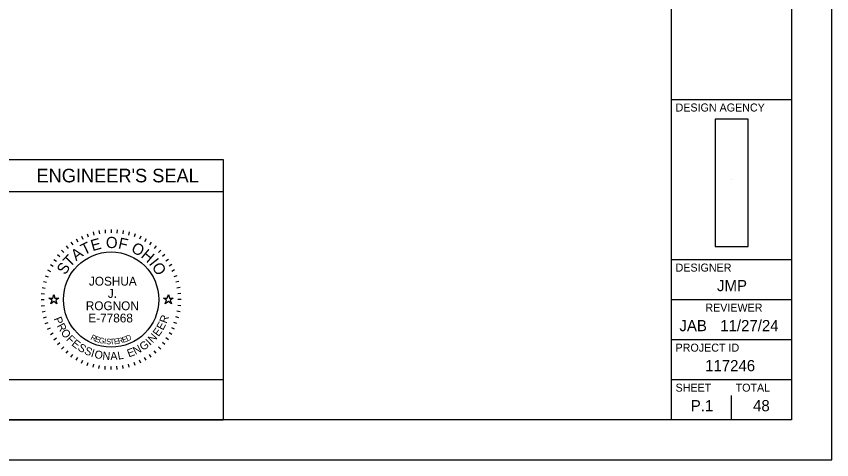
# Model space of a CAD drawing. Extents: x 0 to 34, y 0 to 22.
# Drawn here: x 23.82 to 34, y 0 to 5.54 of the extents above; entities that cross this region are included whole.
import ezdxf

# ---------------------------------------------------------------- set-up
doc = ezdxf.new("R2010")
doc.units = 0
for name, color, linetype in [('Default', 7, 'Continuous'), ('SH_Border', 7, 'Continuous'), ('SH_Cut_Line', 7, 'Continuous'), ('SH_Data', 7, 'Continuous'), ('SH_Text', 7, 'Continuous')]:
    doc.layers.add(name, color=color, linetype=linetype)

msp = doc.modelspace()

# ---------------------------------------------------------------- linework, layer by layer
at = {"layer": 'Default'}
for points in [[(24.224, 2.02), (24.271, 2.02), (24.285, 2.065), (24.299, 2.02), (24.346, 2.02), (24.308, 1.992), (24.323, 1.948), (24.285, 1.975), (24.247, 1.948), (24.262, 1.992)], [(25.654, 2.02), (25.701, 2.02), (25.715, 2.065), (25.729, 2.02), (25.776, 2.02), (25.738, 1.992), (25.753, 1.948), (25.715, 1.975), (25.677, 1.948), (25.692, 1.992)]]:
    msp.add_lwpolyline(points, close=True, dxfattribs=at)
at = {"layer": 'SH_Border'}
for p, q in [((32, 0.5), (32, 21.5)), ((32, 4.5), (33.5, 4.5)), ((32, 2.5), (33.5, 2.5)), ((32, 2), (33.5, 2)), ((32, 1.5), (33.5, 1.5)), ((32, 1), (33.5, 1))]:
    msp.add_line(p, q, dxfattribs=at)
msp.add_lwpolyline([(1.5, 21.5), (33.5, 21.5), (33.5, 0.5), (1.5, 0.5)], close=True, dxfattribs=at)
at = {"layer": 'SH_Cut_Line'}
msp.add_lwpolyline([(0, 0), (34, 0), (34, 22), (0, 22)], close=True, dxfattribs=at)
at = {"layer": 'SH_Data'}
for p, q in [((23.6, 3.75), (26.4, 3.75)), ((26.4, 3.75), (26.4, 0.5)), ((32.75, 3.5), (32.75, 3.5)), ((23.6, 3.35), (26.4, 3.35)), ((24.848, 2.862), (24.855, 2.822)), ((24.924, 2.872), (24.927, 2.832)), ((25, 2.875), (25, 2.835)), ((25.076, 2.872), (25.073, 2.832)), ((25.152, 2.862), (25.145, 2.822)), ((24.563, 2.758), (24.583, 2.723)), ((24.63, 2.793), (24.647, 2.757)), ((24.701, 2.822), (24.714, 2.785)), ((24.774, 2.845), (24.784, 2.807)), ((25.226, 2.845), (25.216, 2.807)), ((25.299, 2.822), (25.286, 2.785)), ((25.37, 2.793), (25.353, 2.757)), ((25.437, 2.758), (25.417, 2.723)), ((24.438, 2.67), (24.463, 2.64)), ((24.498, 2.717), (24.521, 2.684)), ((25.502, 2.717), (25.479, 2.684)), ((25.562, 2.67), (25.537, 2.64)), ((24.33, 2.562), (24.36, 2.537)), ((24.381, 2.619), (24.41, 2.59)), ((25.619, 2.619), (25.59, 2.59)), ((25.67, 2.562), (25.64, 2.537)), ((24.283, 2.502), (24.316, 2.479)), ((25.717, 2.502), (25.684, 2.479)), ((24.207, 2.37), (24.243, 2.353)), ((24.242, 2.438), (24.277, 2.418)), ((25.758, 2.438), (25.723, 2.418)), ((25.793, 2.37), (25.757, 2.353)), ((24.178, 2.299), (24.215, 2.286)), ((25.822, 2.299), (25.785, 2.286)), ((24.138, 2.152), (24.178, 2.145)), ((24.155, 2.226), (24.193, 2.216)), ((25.845, 2.226), (25.807, 2.216)), ((25.862, 2.152), (25.822, 2.145)), ((24.128, 2.076), (24.168, 2.073)), ((25.872, 2.076), (25.832, 2.073)), ((24.125, 2), (24.165, 2)), ((25.875, 2), (25.835, 2)), ((24.128, 1.924), (24.168, 1.927)), ((24.138, 1.848), (24.178, 1.855)), ((25.862, 1.848), (25.822, 1.855)), ((25.872, 1.924), (25.832, 1.927)), ((24.155, 1.774), (24.193, 1.784)), ((25.845, 1.774), (25.807, 1.784)), ((24.178, 1.701), (24.215, 1.714)), ((24.207, 1.63), (24.243, 1.647)), ((25.793, 1.63), (25.757, 1.647)), ((25.822, 1.701), (25.785, 1.714)), ((24.242, 1.563), (24.277, 1.583)), ((25.758, 1.563), (25.723, 1.583)), ((24.283, 1.498), (24.316, 1.521)), ((24.33, 1.438), (24.36, 1.463)), ((25.67, 1.438), (25.64, 1.463)), ((25.717, 1.498), (25.684, 1.521)), ((24.381, 1.381), (24.41, 1.41)), ((24.438, 1.33), (24.463, 1.36)), ((25.562, 1.33), (25.537, 1.36)), ((25.619, 1.381), (25.59, 1.41)), ((24.498, 1.283), (24.521, 1.316)), ((24.563, 1.242), (24.583, 1.277)), ((24.63, 1.207), (24.647, 1.243)), ((25.37, 1.207), (25.353, 1.243)), ((25.437, 1.242), (25.417, 1.277)), ((25.502, 1.283), (25.479, 1.316)), ((24.701, 1.178), (24.714, 1.215)), ((24.774, 1.155), (24.784, 1.193)), ((24.848, 1.138), (24.855, 1.178)), ((24.924, 1.128), (24.927, 1.168)), ((25, 1.125), (25, 1.165)), ((25.076, 1.128), (25.073, 1.168)), ((25.152, 1.138), (25.145, 1.178)), ((25.226, 1.155), (25.216, 1.193)), ((25.299, 1.178), (25.286, 1.215)), ((32.75, 0.5), (32.75, 0.8)), ((32.375, 0.675), (32.375, 0.675)), ((23.6, 0.5), (26.4, 0.5))]:
    msp.add_line(p, q, dxfattribs=at)
msp.add_lwpolyline([(23.6, 0.5), (23.6, 1), (26.4, 1), (26.4, 0.5)], close=True, dxfattribs=at)
msp.add_circle((25, 2), 0.595, dxfattribs=at)
at = {"layer": 'SH_Text'}
msp.add_lwpolyline([(32.956, 2.664), (32.956, 4.254), (32.544, 4.254), (32.544, 2.664)], close=True, dxfattribs=at)

# ---------------------------------------------------------------- texts
at = {"layer": 'SH_Data'}
for s, height, p in [('DESIGN AGENCY', 0.1, (32.05, 4.35)), ("ENGINEER'S SEAL", 0.17, (24.068, 3.465)), ('DESIGNER', 0.1, (32.05, 2.35)), ('JOSHUA', 0.11, (24.723, 2.175)), ('JMP', 0.14, (32.568, 2.105)), ('J.', 0.11, (24.959, 2.022)), ('ROGNON', 0.11, (24.684, 1.868)), ('REVIEWER', 0.1, (32.422, 1.85)), ('E-77868', 0.11, (24.716, 1.715)), ('JAB', 0.14, (32.098, 1.605)), ('11/27/24', 0.14, (32.608, 1.605)), ('PROJECT ID', 0.1, (32.05, 1.35)), ('117246', 0.14, (32.419, 1.105)), ('SHEET', 0.1, (32.05, 0.85)), ('TOTAL', 0.1, (32.8, 0.85)), ('P.1', 0.14, (32.24, 0.605)), ('48', 0.14, (33.018, 0.605))]:
    msp.add_text(s, height=height, dxfattribs=at).set_placement(p)
for s, height, rotation, p in [('E', 0.14, 15.7571, (24.768, 2.604)), ('O', 0.14, 359.7812, (24.935, 2.644)), ('F', 0.14, 347.4362, (25.081, 2.642)), ('T', 0.14, 25.7167, (24.662, 2.552)), ('O', 0.14, 332.2586, (25.24, 2.602)), ('T', 0.14, 46.4344, (24.488, 2.396)), ('A', 0.14, 36.4747, (24.563, 2.478)), ('H', 0.14, 319.9136, (25.363, 2.536)), ('S', 0.14, 57.1924, (24.428, 2.301)), ('I', 0.14, 308.367, (25.466, 2.448)), ('O', 0.14, 303.1491, (25.502, 2.409)), ('P', 0.1, 291.494, (24.282, 1.762)), ('R', 0.1, 69.2322, (25.692, 1.695)), ('R', 0.1, 298.7311, (24.319, 1.672)), ('E', 0.1, 54.758, (25.593, 1.531)), ('E', 0.1, 61.9951, (25.648, 1.61)), ('O', 0.1, 306.4666, (24.365, 1.588)), ('F', 0.1, 314.7068, (24.434, 1.498)), ('R', 0.07, 334.487, (24.737, 1.505)), ('E', 0.07, 341.04, (24.791, 1.48)), ('E', 0.07, 17.6836, (25.15, 1.46)), ('D', 0.07, 23.3052, (25.201, 1.477)), ('N', 0.1, 47.0224, (25.52, 1.451)), ('E', 0.1, 321.4393, (24.498, 1.435)), ('S', 0.1, 328.6764, (24.574, 1.375)), ('G', 0.07, 347.4752, (24.841, 1.462)), ('I', 0.07, 353.7858, (24.909, 1.447)), ('S', 0.07, 356.8926, (24.936, 1.443)), ('T', 0.07, 3.0061, (24.986, 1.439)), ('E', 0.07, 6.0117, (25.039, 1.441)), ('R', 0.07, 11.9184, (25.092, 1.447)), ('N', 0.1, 27.3113, (25.304, 1.308)), ('G', 0.1, 35.0469, (25.398, 1.357)), ('I', 0.1, 43.287, (25.487, 1.421)), ('S', 0.1, 335.9134, (24.656, 1.327)), ('I', 0.1, 343.1505, (24.741, 1.29)), ('O', 0.1, 346.8859, (24.784, 1.275)), ('N', 0.1, 355.1261, (24.889, 1.252)), ('A', 0.1, 2.8617, (24.992, 1.244)), ('L', 0.1, 10.0987, (25.089, 1.249)), ('E', 0.1, 20.0742, (25.221, 1.277))]:
    msp.add_text(s, height=height, rotation=rotation, dxfattribs=at).set_placement(p)

doc.saveas('drawing.dxf')
